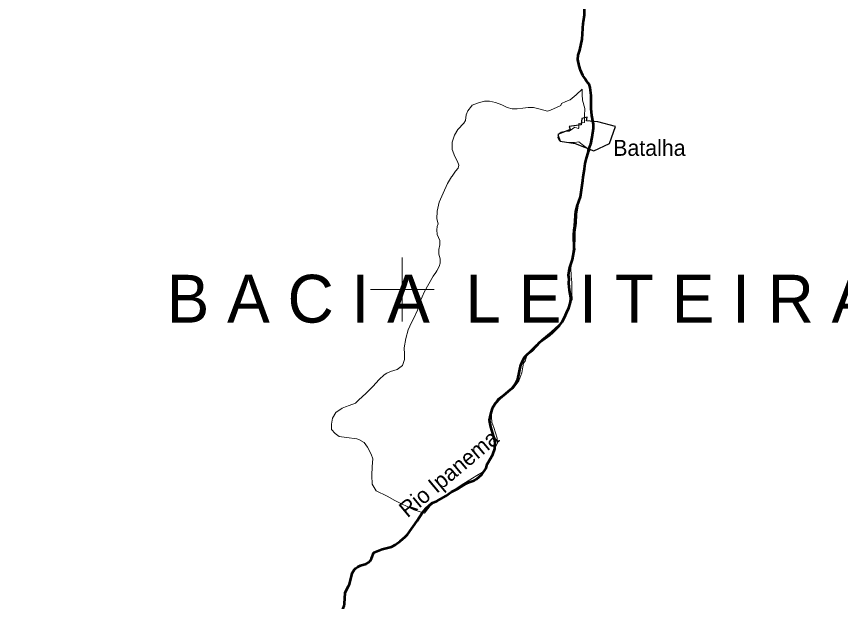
# Model space of a CAD drawing. Extents: x -1643653 to 4543381, y 1624270 to 13878484.
# Drawn here: x 687907 to 713736, y 8915212 to 8933563 of the extents above; entities that cross this region are included whole.
import ezdxf
from ezdxf.enums import TextEntityAlignment as Align

# ---------------------------------------------------------------- set-up
doc = ezdxf.new("R2010")
doc.units = 0
doc.header["$LTSCALE"] = 160
for name, color, linetype, lineweight in [('2', 7, 'Continuous', 13), ('21', 7, 'Continuous', 25), ('24', 7, 'Continuous', 25), ('52', 7, 'Continuous', 13), ('60', 7, 'Continuous', 13)]:
    doc.layers.add(name, color=color, linetype=linetype, lineweight=lineweight)
for name, color, linetype in [('41', 7, 'Continuous'), ('42', 7, 'Continuous'), ('49', 7, 'Continuous')]:
    doc.layers.add(name, color=color, linetype=linetype)

msp = doc.modelspace()

# ---------------------------------------------------------------- linework, layer by layer
at = {"layer": '2'}
for p, q in [((700000, 8924000), (700000, 8926000)), ((699000, 8925000), (701000, 8925000))]:
    msp.add_line(p, q, dxfattribs=at)
at = {"layer": '21'}
msp.add_lwpolyline([(706124.6, 8930262.6), (705772.7, 8930291), (705798.2, 8930406.1), (705622.6, 8930367.7), (705604.9, 8930160.7), (705235.9, 8930107), (705266.5, 8930017.5), (704872.7, 8929859.6), (704949.4, 8929648.4), (705414.2, 8929583), (706002.8, 8929352.6), (706496.2, 8929580.5), (706680.1, 8930116.3)], close=True, dxfattribs=at)
at = {"layer": '24', "lineweight": 53}
for points in [[(705678, 8933377.8), (705684.3, 8933403.1), (705709.2, 8933609.6), (705711.7, 8934031.1), (705741.1, 8934209.4), (705803.6, 8934425.7), (705881, 8934596.9), (705904.4, 8934674.1)], [(705923, 8930675.2), (705922.4, 8931088), (705890.3, 8931333.3), (705852.8, 8931442.3), (705831.3, 8931475.9), (705777.1, 8931528.7), (705743, 8931598.9), (705663.1, 8931713.6), (705581.9, 8931877.1), (705542.5, 8932009.4), (705503.3, 8932209.2), (705508.2, 8932351.5), (705569.4, 8932508), (705640.5, 8932849.9), (705671.7, 8933352.4), (705678, 8933377.8)], [(705981.1, 8930233.2), (705937.6, 8930459), (705923, 8930675.2)], [(705906.7, 8929556.8), (705952.7, 8929774.7), (705995, 8930056.4), (705991.2, 8930180.9), (705981.1, 8930233.2)], [(705714.4, 8928785), (705737.3, 8928951.8), (705774, 8929122.5), (705823.8, 8929288.7), (705837.1, 8929367.7), (705902.7, 8929538.2), (705906.7, 8929556.8)], [(705581.6, 8927900.5), (705661.4, 8928419), (705668.1, 8928525.9), (705714.4, 8928785)], [(705429.5, 8927325.7), (705443, 8927442.9), (705477.8, 8927613.5), (705581.6, 8927900.5)], [(703328.7, 8921805.4), (703443, 8921908.1), (703548.7, 8922036.8), (703617.1, 8922184), (703718.8, 8922634.2), (703746.2, 8922702.2), (703835.8, 8922872.4), (703941.7, 8922992.8), (704066.1, 8923087.4), (704318, 8923358.7), (704612.5, 8923568.7), (704719.2, 8923658.3), (704922.8, 8923872.7), (705008.7, 8923982.7), (705085.3, 8924116.9), (705144.1, 8924270.4), (705217.1, 8924423.9), (705261.2, 8924562.9), (705283, 8924679.2), (705282.9, 8924744.8), (705239.7, 8924977.1), (705221.2, 8925199.9), (705230.3, 8925333.3), (705211.7, 8925444.3), (705241.2, 8925661.6), (705335.2, 8925935.9), (705376.3, 8926171.8), (705383.6, 8926283.7), (705379.5, 8926700.1), (705390.8, 8926871), (705410.9, 8927000.7), (705427.2, 8927305.4), (705429.5, 8927325.7)], [(700933.1, 8918304.1), (701087.7, 8918357.1), (701353.2, 8918514.3), (701545, 8918649.8), (701747.7, 8918756.1), (702001.1, 8918916), (702097.1, 8918956.4), (702250.9, 8919005.3), (702331, 8919046.8), (702493.5, 8919198.3), (702630.7, 8919399.1), (702659.6, 8919524.5), (702838.4, 8919824.3), (702905.9, 8919998.5), (702914.2, 8920160.2), (702900, 8920271.5), (702779.5, 8920686.8), (702738.4, 8920898.1), (702772.1, 8921093.7), (702813.3, 8921239.1), (702844.7, 8921319.1), (702917.3, 8921435.8), (703064, 8921594.2), (703249.3, 8921734.1), (703328.7, 8921805.4)], [(699106, 8916749.2), (699107.9, 8916751.8), (699364.4, 8916858.8), (699663.1, 8916929.4), (699774, 8916985.7), (699929.5, 8917100.9), (700086.2, 8917240.2), (700161.8, 8917318.8), (700161.8, 8917318.8), (700462.7, 8917739.7), (700633.3, 8918009.2), (700747.4, 8918139), (700925.2, 8918301.4), (700933.1, 8918304.1)], [(698310.3, 8915692), (698345.2, 8915759.1), (698414.2, 8916049.1), (698434, 8916103.3), (698493.2, 8916205.4), (698541, 8916255.4), (698604.5, 8916300.2), (698689, 8916338.6), (698872.4, 8916392.4), (698958.8, 8916447.6), (698989, 8916484.6), (699031.1, 8916558.4), (699106, 8916749.2)], [(698089.5, 8914668.2), (698093, 8914730.9), (698057.9, 8914805.5), (698057.7, 8914860.2), (698080.5, 8914908.2), (698146.1, 8914998.1), (698179.3, 8915082.2), (698193.2, 8915143.2), (698213.4, 8915483.8), (698249.4, 8915574.9), (698249.4, 8915574.9), (698310.3, 8915692)]]:
    msp.add_lwpolyline(points, dxfattribs=at)
at = {"layer": '24'}
for points in [[(705581.6, 8927900.5), (705661.4, 8928419), (705668.1, 8928525.9), (705714.4, 8928785)], [(705429.5, 8927325.7), (705443, 8927442.9), (705477.8, 8927613.5), (705581.6, 8927900.5)], [(703328.7, 8921805.4), (703443, 8921908.1), (703548.7, 8922036.8), (703617.1, 8922184), (703718.8, 8922634.2), (703746.2, 8922702.2), (703835.8, 8922872.4), (703941.7, 8922992.8), (704066.1, 8923087.4), (704318, 8923358.7), (704612.5, 8923568.7), (704719.2, 8923658.3), (704922.8, 8923872.7), (705008.7, 8923982.7), (705085.3, 8924116.9), (705144.1, 8924270.4), (705217.1, 8924423.9), (705261.2, 8924562.9), (705283, 8924679.2), (705282.9, 8924744.8), (705239.7, 8924977.1), (705221.2, 8925199.9), (705230.3, 8925333.3), (705211.7, 8925444.3), (705241.2, 8925661.6), (705335.2, 8925935.9), (705376.3, 8926171.8), (705383.6, 8926283.7), (705379.5, 8926700.1), (705390.8, 8926871), (705410.9, 8927000.7), (705427.2, 8927305.4), (705429.5, 8927325.7)], [(700933.1, 8918304.1), (701087.7, 8918357.1), (701353.2, 8918514.3), (701545, 8918649.8), (701747.7, 8918756.1), (702001.1, 8918916), (702097.1, 8918956.4), (702250.9, 8919005.3), (702331, 8919046.8), (702493.5, 8919198.3), (702630.7, 8919399.1), (702659.6, 8919524.5), (702838.4, 8919824.3), (702905.9, 8919998.5), (702914.2, 8920160.2), (702900, 8920271.5), (702779.5, 8920686.8), (702738.4, 8920898.1), (702772.1, 8921093.7), (702813.3, 8921239.1), (702844.7, 8921319.1), (702917.3, 8921435.8), (703064, 8921594.2), (703249.3, 8921734.1), (703328.7, 8921805.4)], [(699106, 8916749.2), (699107.9, 8916751.8), (699364.4, 8916858.8), (699663.1, 8916929.4), (699774, 8916985.7), (699929.5, 8917100.9), (700086.2, 8917240.2), (700161.8, 8917318.8), (700161.8, 8917318.8), (700462.7, 8917739.7), (700633.3, 8918009.2), (700747.4, 8918139), (700925.2, 8918301.4), (700933.1, 8918304.1)], [(698310.3, 8915692), (698345.2, 8915759.1), (698414.2, 8916049.1), (698434, 8916103.3), (698493.2, 8916205.4), (698541, 8916255.4), (698604.5, 8916300.2), (698689, 8916338.6), (698872.4, 8916392.4), (698958.8, 8916447.6), (698989, 8916484.6), (699031.1, 8916558.4), (699106, 8916749.2)], [(698089.5, 8914668.2), (698093, 8914730.9), (698057.9, 8914805.5), (698057.7, 8914860.2), (698080.5, 8914908.2), (698146.1, 8914998.1), (698179.3, 8915082.2), (698193.2, 8915143.2), (698213.4, 8915483.8), (698249.4, 8915574.9), (698249.4, 8915574.9), (698310.3, 8915692)]]:
    msp.add_lwpolyline(points, dxfattribs=at)
at = {"layer": '52'}
for points in [[(704553.1, 8930592.5), (704645.5, 8930626.1), (704851.5, 8930715.5), (704967.9, 8930769.2), (704994.7, 8930831.8), (705129, 8930894.4), (705263.3, 8930948), (705451.4, 8931109), (705639.4, 8931278.9), (705635.1, 8931118.9), (705653, 8930940.1), (705724.6, 8930680.7), (705715.7, 8930448.2), (705715.7, 8930233.6), (705536.2, 8930202.8), (705536.2, 8930068.6), (705509.3, 8930050.7), (705410.9, 8930086.5), (705330.3, 8930041.8), (705231.8, 8929970.3), (705115.4, 8929970.3), (704981.1, 8929934.5), (704891.5, 8929871.9), (704873.6, 8929755.6)], [(704553.1, 8930592.5), (704645.5, 8930626.1), (704851.5, 8930715.5), (704967.9, 8930769.2), (704994.7, 8930831.8), (705129, 8930894.4), (705263.3, 8930948), (705451.4, 8931109), (705639.4, 8931278.9), (705635.1, 8931118.9), (705653, 8930940.1), (705724.6, 8930680.7), (705715.7, 8930448.2), (705715.7, 8930233.6), (705536.2, 8930202.8), (705536.2, 8930068.6), (705509.3, 8930050.7), (705410.9, 8930086.5), (705330.3, 8930041.8), (705231.8, 8929970.3), (705115.4, 8929970.3), (704981.1, 8929934.5), (704891.5, 8929871.9), (704873.6, 8929755.6)], [(704873.6, 8929755.6), (704891.5, 8929871.9), (704981.1, 8929934.5), (705115.4, 8929970.3), (705231.8, 8929970.3), (705330.3, 8930041.8), (705410.9, 8930086.5), (705509.3, 8930050.7), (705536.2, 8930068.6), (705536.2, 8930202.8), (705715.7, 8930233.6), (705715.7, 8930448.2), (705724.6, 8930680.7), (705653, 8930940.1), (705635.1, 8931118.9), (705639.4, 8931278.9), (705451.4, 8931109), (705263.3, 8930948), (705129, 8930894.4), (704994.7, 8930831.8), (704967.9, 8930769.2), (704851.5, 8930715.5), (704645.5, 8930626.1), (704553.1, 8930592.5)], [(701561.1, 8928552.9), (701672.8, 8928712.3), (701753.4, 8928801.7), (701771.3, 8928900.1), (701726.6, 8929016.3), (701646, 8929168.4), (701565.4, 8929391.9), (701565.4, 8929615.5), (701637, 8929839.1), (701744.5, 8930018), (701925.4, 8930217.4), (701986.2, 8930304.1), (702004.1, 8930474.1), (702057.8, 8930608.2), (702167.3, 8930746.7)], [(701561.1, 8928552.9), (701672.8, 8928712.3), (701753.4, 8928801.7), (701771.3, 8928900.1), (701726.6, 8929016.3), (701646, 8929168.4), (701565.4, 8929391.9), (701565.4, 8929615.5), (701637, 8929839.1), (701744.5, 8930018), (701925.4, 8930217.4), (701986.2, 8930304.1), (702004.1, 8930474.1), (702057.8, 8930608.2), (702167.3, 8930746.7)], [(702167.3, 8930746.7), (702057.8, 8930608.2), (702004.1, 8930474.1), (701986.2, 8930304.1), (701925.4, 8930217.4), (701744.5, 8930018), (701637, 8929839.1), (701565.4, 8929615.5), (701565.4, 8929391.9), (701646, 8929168.4), (701726.6, 8929016.3), (701771.3, 8928900.1), (701753.4, 8928801.7), (701672.8, 8928712.3), (701561.1, 8928552.9)], [(702167.3, 8930746.7), (702192.2, 8930778.1), (702389.1, 8930858.6), (702577.2, 8930903.3), (702729.4, 8930903.3), (702926.4, 8930867.6), (703123.3, 8930787.1), (703284.5, 8930706.6), (703445.7, 8930670.8), (703553.4, 8930664.5)], [(702167.3, 8930746.7), (702192.2, 8930778.1), (702389.1, 8930858.6), (702577.2, 8930903.3), (702729.4, 8930903.3), (702926.4, 8930867.6), (703123.3, 8930787.1), (703284.5, 8930706.6), (703445.7, 8930670.8), (703553.4, 8930664.5)], [(703553.4, 8930664.5), (703445.7, 8930670.8), (703284.5, 8930706.6), (703123.3, 8930787.1), (702926.4, 8930867.6), (702729.4, 8930903.3), (702577.2, 8930903.3), (702389.1, 8930858.6), (702192.2, 8930778.1), (702167.3, 8930746.7)], [(703553.4, 8930664.5), (703597.9, 8930661.9), (703777, 8930688.7), (703947.1, 8930706.6), (704108.3, 8930706.6), (704323.2, 8930652.9)], [(703553.4, 8930664.5), (703597.9, 8930661.9), (703777, 8930688.7), (703947.1, 8930706.6), (704108.3, 8930706.6), (704323.2, 8930652.9)], [(704323.2, 8930652.9), (704108.3, 8930706.6), (703947.1, 8930706.6), (703777, 8930688.7), (703597.9, 8930661.9), (703553.4, 8930664.5)], [(704323.2, 8930652.9), (704547, 8930590.3), (704553.1, 8930592.5)], [(704323.2, 8930652.9), (704547, 8930590.3), (704553.1, 8930592.5)], [(704553.1, 8930592.5), (704547, 8930590.3), (704323.2, 8930652.9)], [(704873.6, 8929755.6), (704927.3, 8929666.2), (705052.7, 8929630.4), (705222.8, 8929612.5), (705401.9, 8929612.5), (705536.2, 8929630.4), (705637.2, 8929550.8), (705759.7, 8929454.2), (705876.5, 8929362.1), (705795.9, 8929183.3), (705742.2, 8928932.9), (705688.4, 8928646.7), (705643.7, 8928342.6), (705598.9, 8928065.4), (705527, 8927674.5), (705473.2, 8927361.5), (705464.3, 8927084.2), (705419.5, 8926798.1), (705419.5, 8926529.8), (705401.6, 8926359.8), (705419.5, 8926261.5), (705374.7, 8926055.8), (705321, 8925868), (705312.9, 8925825.5)], [(704873.6, 8929755.6), (704927.3, 8929666.2), (705052.7, 8929630.4), (705222.8, 8929612.5), (705401.9, 8929612.5), (705536.2, 8929630.4), (705637.2, 8929550.8), (705759.7, 8929454.2), (705876.5, 8929362.1), (705795.9, 8929183.3), (705742.2, 8928932.9), (705688.4, 8928646.7), (705643.7, 8928342.6), (705598.9, 8928065.4), (705527, 8927674.5), (705473.2, 8927361.5), (705464.3, 8927084.2), (705419.5, 8926798.1), (705419.5, 8926529.8), (705401.6, 8926359.8), (705419.5, 8926261.5), (705374.7, 8926055.8), (705321, 8925868), (705312.9, 8925825.5)], [(705637.2, 8929550.8), (705536.2, 8929630.4), (705401.9, 8929612.5), (705222.8, 8929612.5), (705052.7, 8929630.4), (704927.3, 8929666.2), (704873.6, 8929755.6)], [(705276.5, 8924574.1), (705321, 8924678.6), (705312.1, 8924902.1), (705312.1, 8925215.1), (705294.2, 8925429.8), (705285.2, 8925680.2), (705312.9, 8925825.5), (705321, 8925868), (705374.7, 8926055.8), (705419.5, 8926261.5), (705401.6, 8926359.8), (705419.5, 8926529.8), (705419.5, 8926798.1), (705464.3, 8927084.2), (705473.2, 8927361.5), (705527, 8927674.5), (705598.9, 8928065.4), (705643.7, 8928342.6), (705688.4, 8928646.7), (705742.2, 8928932.9), (705795.9, 8929183.3), (705876.5, 8929362.1), (705759.7, 8929454.2), (705637.2, 8929550.8)], [(701561.1, 8928552.9), (701547.5, 8928533.4), (701413.2, 8928327.7), (701286.5, 8928016.8), (701161.1, 8927739.6), (701098.4, 8927453.4), (701080.5, 8927211.9), (701125.3, 8927059.9), (701098.4, 8926970.5), (701080.5, 8926872.1), (701098.4, 8926720.1), (701179, 8926532.3), (701179, 8926398.1), (701143.2, 8926255), (701143.2, 8926103), (701188, 8925959.9), (701188, 8925825.8), (701152.2, 8925718.4), (701080.5, 8925584.3), (701050.8, 8925537.3), (700973.1, 8925414.4), (700694.8, 8924934.2), (700551.5, 8924603.3), (700479.9, 8924352.9), (700336.6, 8924057.7), (700292.8, 8923965), (700184.4, 8923735.8), (700112.8, 8923458.6), (700059.1, 8923172.4), (700068, 8922966.7), (700067.3, 8922798.3), (700004.7, 8922619.4), (699834.5, 8922494.2), (699628.6, 8922431.6), (699519.3, 8922372.1), (699431.6, 8922324.3), (699279.4, 8922181.2), (699073.4, 8921957.7), (698858.6, 8921734.1), (698639.4, 8921533.7)], [(701050.8, 8925537.3), (701080.5, 8925584.3), (701152.2, 8925718.4), (701188, 8925825.8), (701188, 8925959.9), (701143.2, 8926103), (701143.2, 8926255), (701179, 8926398.1), (701179, 8926532.3), (701098.4, 8926720.1), (701080.5, 8926872.1), (701098.4, 8926970.5), (701125.3, 8927059.9), (701080.5, 8927211.9), (701098.4, 8927453.4), (701161.1, 8927739.6), (701286.5, 8928016.8), (701413.2, 8928327.7), (701547.5, 8928533.4), (701561.1, 8928552.9)], [(701050.8, 8925537.3), (701080.5, 8925584.3), (701152.2, 8925718.4), (701188, 8925825.8), (701188, 8925959.9), (701143.2, 8926103), (701143.2, 8926255), (701179, 8926398.1), (701179, 8926532.3), (701098.4, 8926720.1), (701080.5, 8926872.1), (701098.4, 8926970.5), (701125.3, 8927059.9), (701080.5, 8927211.9), (701098.4, 8927453.4), (701161.1, 8927739.6), (701286.5, 8928016.8), (701413.2, 8928327.7), (701547.5, 8928533.4), (701561.1, 8928552.9)], [(705312.9, 8925825.5), (705285.2, 8925680.2), (705294.2, 8925429.8), (705312.1, 8925215.1), (705312.1, 8924902.1), (705321, 8924678.6), (705276.5, 8924574.1), (705276.5, 8924574.1), (705229.7, 8924464.4), (705068.5, 8924061.9), (704907.3, 8923892), (704665.6, 8923668.4), (704379, 8923427), (704065.7, 8923131.9), (703931.3, 8922997.7), (703904.5, 8922926.2), (703850.8, 8922756.3), (703797, 8922693.7), (703779.1, 8922577.4), (703752.3, 8922380.7), (703653.8, 8922130.2), (703474.7, 8921888.8), (703231.4, 8921748.3), (702998.6, 8921569.4), (702882.2, 8921399.5), (702801.7, 8921211.7), (702792.7, 8920997.1), (702810.6, 8920836.1), (702864.3, 8920666.2), (702971.8, 8920335.3), (702980.7, 8920174.3), (702918.1, 8920049.1), (702783.7, 8919745), (702649.4, 8919432), (702515.1, 8919271.1), (702339.9, 8919165.6), (701928, 8918915.2), (701498.2, 8918629), (701131.1, 8918423.3), (700871.4, 8918208.7)], [(705312.9, 8925825.5), (705285.2, 8925680.2), (705294.2, 8925429.8), (705312.1, 8925215.1), (705312.1, 8924902.1), (705321, 8924678.6), (705276.5, 8924574.1), (705276.5, 8924574.1), (705229.7, 8924464.4), (705068.5, 8924061.9), (704907.3, 8923892), (704665.6, 8923668.4), (704379, 8923427), (704065.7, 8923131.9), (703931.3, 8922997.7), (703904.5, 8922926.2), (703850.8, 8922756.3), (703797, 8922693.7), (703779.1, 8922577.4), (703752.3, 8922380.7), (703653.8, 8922130.2), (703474.7, 8921888.8), (703231.4, 8921748.3), (702998.6, 8921569.4), (702882.2, 8921399.5), (702801.7, 8921211.7), (702792.7, 8920997.1), (702810.6, 8920836.1), (702864.3, 8920666.2), (702971.8, 8920335.3), (702980.7, 8920174.3), (702918.1, 8920049.1), (702783.7, 8919745), (702649.4, 8919432), (702515.1, 8919271.1), (702339.9, 8919165.6), (701928, 8918915.2), (701498.2, 8918629), (701131.1, 8918423.3), (700871.4, 8918208.7)], [(700112.8, 8923458.6), (700184.4, 8923735.8), (700292.8, 8923965), (700336.6, 8924057.7), (700479.9, 8924352.9), (700551.5, 8924603.3), (700694.8, 8924934.2), (700973.1, 8925414.4), (701050.8, 8925537.3)], [(700112.8, 8923458.6), (700184.4, 8923735.8), (700292.8, 8923965), (700336.6, 8924057.7), (700479.9, 8924352.9), (700551.5, 8924603.3), (700694.8, 8924934.2), (700973.1, 8925414.4), (701050.8, 8925537.3)], [(702810.6, 8920836.1), (702792.7, 8920997.1), (702801.7, 8921211.7), (702882.2, 8921399.5), (702998.6, 8921569.4), (703231.4, 8921748.3), (703474.7, 8921888.8), (703653.8, 8922130.2), (703752.3, 8922380.7), (703779.1, 8922577.4), (703797, 8922693.7), (703850.8, 8922756.3), (703904.5, 8922926.2), (703931.3, 8922997.7), (704065.7, 8923131.9), (704379, 8923427), (704665.6, 8923668.4), (704907.3, 8923892), (705068.5, 8924061.9), (705229.7, 8924464.4), (705276.5, 8924574.1), (705276.5, 8924574.1)], [(700871.4, 8918208.7), (700692.3, 8917985.1), (700361.1, 8918083.5), (699769.2, 8918382), (699528.3, 8918512.7), (699185.6, 8918680.8), (699060.2, 8918895.5), (699042.3, 8919163.8), (699060.2, 8919449.9), (699078.2, 8919691.4), (699024.4, 8919834.5), (698908, 8920049.1), (698809.5, 8920201.2), (698633, 8920289.3), (698576.7, 8920317.4), (698254.4, 8920362.1), (698021.6, 8920388.9), (697896.2, 8920487.3), (697779.8, 8920612.5), (697779.8, 8920773.5), (697815.7, 8920961.3), (697914.2, 8921140.2), (698120.1, 8921274.3), (698217.8, 8921315), (698217.8, 8921315), (698335, 8921363.7), (698532, 8921435.3), (698639.4, 8921533.7), (698858.6, 8921734.1), (699073.4, 8921957.7), (699279.4, 8922181.2), (699431.6, 8922324.3), (699519.3, 8922372.1), (699628.6, 8922431.6), (699834.5, 8922494.2), (700004.7, 8922619.4), (700067.3, 8922798.3), (700068, 8922966.7), (700059.1, 8923172.4), (700112.8, 8923458.6)], [(700871.4, 8918208.7), (700692.3, 8917985.1), (700361.1, 8918083.5), (699769.2, 8918382), (699528.3, 8918512.7), (699185.6, 8918680.8), (699060.2, 8918895.5), (699042.3, 8919163.8), (699060.2, 8919449.9), (699078.2, 8919691.4), (699024.4, 8919834.5), (698908, 8920049.1), (698809.5, 8920201.2), (698633, 8920289.3), (698576.7, 8920317.4), (698254.4, 8920362.1), (698021.6, 8920388.9), (697896.2, 8920487.3), (697779.8, 8920612.5), (697779.8, 8920773.5), (697815.7, 8920961.3), (697914.2, 8921140.2), (698120.1, 8921274.3), (698217.8, 8921315), (698217.8, 8921315), (698335, 8921363.7), (698532, 8921435.3), (698639.4, 8921533.7), (698858.6, 8921734.1), (699073.4, 8921957.7), (699279.4, 8922181.2), (699431.6, 8922324.3), (699519.3, 8922372.1), (699628.6, 8922431.6), (699834.5, 8922494.2), (700004.7, 8922619.4), (700067.3, 8922798.3), (700068, 8922966.7), (700059.1, 8923172.4), (700112.8, 8923458.6)], [(698639.4, 8921533.7), (698532, 8921435.3), (698335, 8921363.7), (698217.8, 8921315), (698217.8, 8921315), (698120.1, 8921274.3), (697914.2, 8921140.2), (697815.7, 8920961.3), (697779.8, 8920773.5), (697779.8, 8920612.5), (697896.2, 8920487.3), (698021.6, 8920388.9), (698254.4, 8920362.1), (698576.7, 8920317.4), (698633, 8920289.3), (698809.5, 8920201.2), (698908, 8920049.1), (699024.4, 8919834.5), (699078.2, 8919691.4), (699060.2, 8919449.9), (699042.3, 8919163.8), (699060.2, 8918895.5), (699185.6, 8918680.8), (699528.3, 8918512.7), (699769.2, 8918382), (700361.1, 8918083.5), (700692.3, 8917985.1), (700871.4, 8918208.7), (701131.1, 8918423.3), (701498.2, 8918629), (701928, 8918915.2), (702339.9, 8919165.6), (702515.1, 8919271.1), (702649.4, 8919432), (702783.7, 8919745), (702918.1, 8920049.1), (702980.7, 8920174.3), (702971.8, 8920335.3), (702864.3, 8920666.2), (702810.6, 8920836.1)]]:
    msp.add_lwpolyline(points, dxfattribs=at)
at = {"layer": '60', "lineweight": 25}
msp.add_spline([(814781, 9009175.5), (814787.2, 9009173.4), (814796.9, 9009173.4), (814799.4, 9009172.4), (814805.1, 9009174.5), (814805.6, 9009176.5), (814811.7, 9009179.5), (814811.7, 9009179.5), (814801.5, 9009181), (814790.7, 9009181.5), (814784.1, 9009183.1), (814777.4, 9009185.1), (814778.4, 9009175.5)], degree=3, dxfattribs=at)

# ---------------------------------------------------------------- texts
at = {"layer": '41'}
msp.add_text('Batalha', height=500, dxfattribs=at).set_placement((706611.1, 8929191.2))
at = {"layer": '42'}
msp.add_text('B A C I A  L E I T E I R A', height=1500, dxfattribs=at).set_placement((703704.8, 8923960), align=Align.CENTER)
at = {"layer": '49'}
msp.add_text('Rio Ipanema', height=500, rotation=39.92, dxfattribs=at).set_placement((701615.3, 8919036.7), align=Align.CENTER)

doc.saveas('drawing.dxf')
